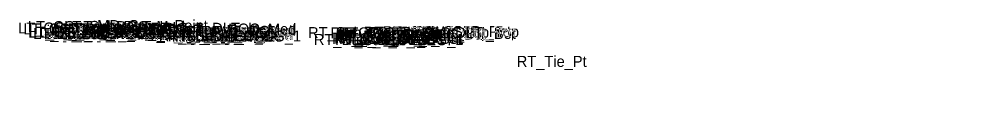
# Model space of a CAD drawing. Extents: x -26 to 4229, y -10 to 9523.
# Drawn here: x 2122.8 to 2300, y 0 to 16.8 of the extents above; entities that cross this region are included whole.
import ezdxf

# ---------------------------------------------------------------- set-up
doc = ezdxf.new("R2010")
doc.units = 0
doc.layers.add('Default', color=7, linetype='Continuous')

msp = doc.modelspace()

# ---------------------------------------------------------------- texts
at = {"layer": 'Default'}
for s, height, p in [('LT_CG_Top_Face_Med', 2, (2122.62, 14.23)), ('LT_CG_Top_Gut_Med', 2, (2123.6, 14.06)), ('LT_CG_Top_BOC_Med', 2, (2124.4, 14.48)), ('LT_PV1_PGL', 2, (2130.28, 14.08)), ('LT_Sub_DLT_In', 2, (2131.03, 14.52)), ('MD_Crown Point', 2, (2137.07, 14.68)), ('RT_CG_Top_BOC_Med', 2, (2144.34, 14.04)), ('RT_Sub_DLT_In', 2, (2146.79, 14.18)), ('LT_CG_Bot_BOC_Med', 2, (2124.44, 13.47)), ('LT_CG_Bot_IE_Med', 2, (2124.56, 13.5)), ('LT_Sub_IEOT_CG_1', 2, (2125.37, 13.25)), ('LT_Sub_OEEOP', 2, (2127.71, 13.2)), ('LT_PV2_OEEOP', 2, (2127.81, 13.83)), ('LT_PV3_OEEOP', 2, (2127.81, 13.58)), ('LT_Sub_IEEOP', 2, (2128.36, 13.2)), ('LT_PV2_IEEOP', 2, (2128.45, 13.83)), ('LT_CG1_Shelf_In', 2, (2128.68, 13.46)), ('LT_Sub_PGL', 2, (2129.62, 13.2)), ('LT_PV2_PGL', 2, (2129.71, 13.83)), ('LT_Sub_IEOP', 2, (2131.52, 13.2)), ('RT_CG_Top_Face_Med', 2, (2144.07, 13.79)), ('RT_CG_Bot_BOC_Med', 2, (2144.37, 13.06)), ('RT_CG_Top_Gut_Med', 2, (2145.05, 13.62)), ('RT_CG_Bot_IE_Med', 2, (2147.52, 13.02)), ('RT_CG1_Shelf_In', 2, (2147.62, 13.07)), ('RT_Sub_IEOT_CG_1', 2, (2148.32, 12.77)), ('RT_Sub_IEOP', 2, (2149.95, 12.82)), ('RT_Sub_OEEOP', 2, (2150.67, 12.73)), ('RT_PV2_OEEOP', 2, (2150.76, 13.36)), ('RT_PV3_OEEOP', 2, (2150.76, 13.11)), ('RT_Sub_IEEOP', 2, (2151.31, 12.73)), ('RT_PV2_IEEOP', 2, (2151.41, 13.36)), ('RT_Sub_PGL', 2, (2152.57, 12.73)), ('RT_PV2_PGL', 2, (2152.67, 13.36)), ('RT_PV1_PGL', 2, (2153.23, 13.61)), ('RT_Sub_Trench_Out_DLT', 2, (2175.6, 13.39)), ('RT_Sub_OEOT_CG_1', 2, (2176.67, 12.14)), ('RT_CG_Top_Face', 2, (2179.71, 13.35)), ('RT_CG1_Shelf_Out', 2, (2180, 12.33)), ('RT_CG_Bot_IE', 2, (2180.37, 12.39)), ('RT_Sub_OEOT', 2, (2180.53, 12.1)), ('RT_PV2_OEOT', 2, (2180.63, 12.72)), ('RT_PV3_OEOT', 2, (2180.63, 12.47)), ('RT_CG_Top_Gut', 2, (2180.69, 12.85)), ('RT_PV1_OEOT', 2, (2181.19, 12.97)), ('RT_CG_Top_BOC', 2, (2181.24, 13.35)), ('RT_CG_Bot_BOC', 2, (2181.27, 12.34)), ('RT_Sub_OEOP', 2, (2183.82, 12.07)), ('RT_SDWK_In_Top', 2, (2185.81, 13.46)), ('RT_SDWK_In_Bot', 2, (2185.84, 13.13)), ('RT_SDWK_Out_Top', 2, (2189.19, 13.56)), ('RT_SDWK_Out_Bot', 2, (2189.22, 13.23)), ('RT_CSLP_Pnt', 2, (2195.13, 13.59)), ('RT_Tie_Pt', 2, (2213.75, 8.14)), ('-', 0.0001, (2300, 0))]:
    msp.add_text(s, height=height, dxfattribs=at).set_placement(p)

doc.saveas('drawing.dxf')
